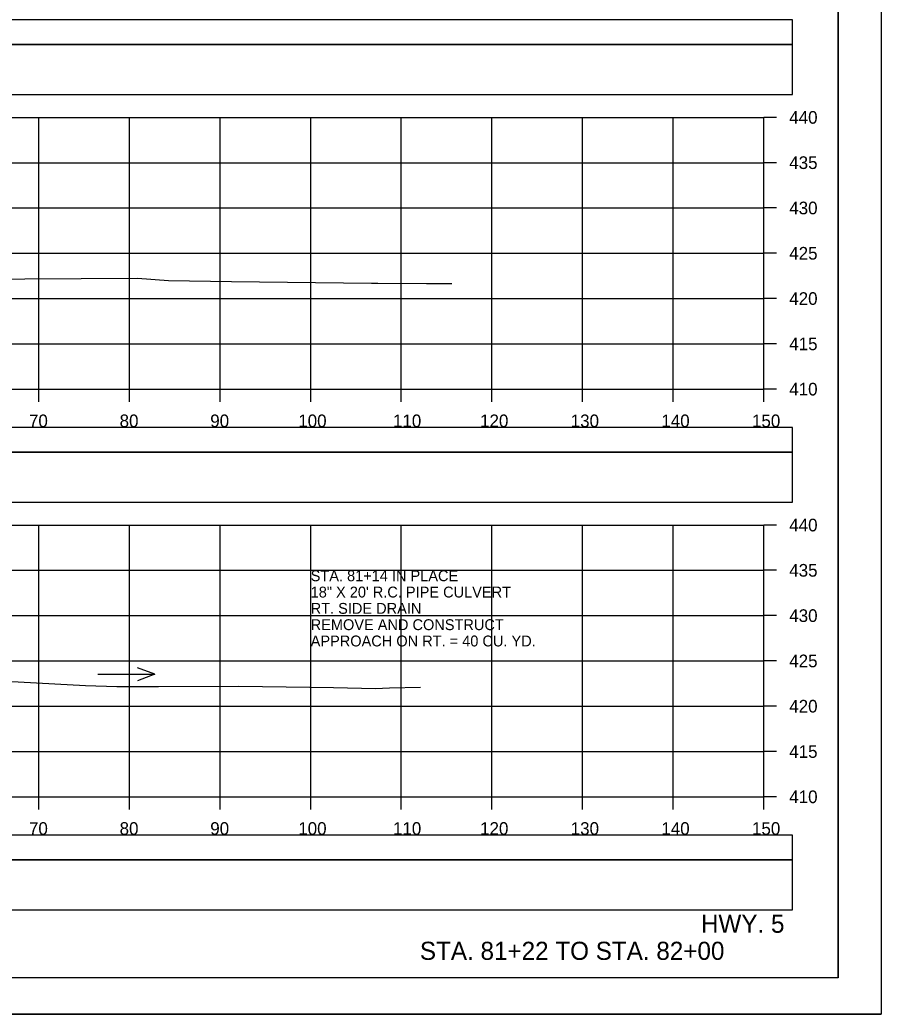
# Model space of a CAD drawing. Extents: x 1371057 to 1372761, y 380005 to 390517.
# Drawn here: x 1371628.8 to 1371723.8, y 387898.6 to 388008.3 of the extents above; entities that cross this region are included whole.
import ezdxf

# ---------------------------------------------------------------- set-up
doc = ezdxf.new("R2010")
doc.units = 0
for name, color, linetype in [('R_Axis', 7, 'Continuous'), ('R_Axis Annot', 7, 'Continuous'), ('R_Border', 7, 'Continuous'), ('R_Detour', 7, 'Continuous'), ('R_Dimension', 7, 'Continuous'), ('R_Draft', 7, 'Continuous'), ('R_Exist Surface', 7, 'Continuous'), ('R_Grid', 7, 'Continuous'), ('R_No Plot', 7, 'Continuous'), ('R_Water Annot', 7, 'Continuous')]:
    doc.layers.add(name, color=color, linetype=linetype)

msp = doc.modelspace()

# ---------------------------------------------------------------- linework, layer by layer
at = {"layer": 'R_Axis'}
for p, q in [((1371710.87, 387967.57), (1371710.87, 387997.57)), ((1371712.27, 387997.57), (1371710.87, 387997.57)), ((1371712.27, 387992.57), (1371710.87, 387992.57)), ((1371712.27, 387987.57), (1371710.87, 387987.57)), ((1371712.27, 387982.57), (1371710.87, 387982.57)), ((1371712.27, 387977.57), (1371710.87, 387977.57)), ((1371712.27, 387972.57), (1371710.87, 387972.57)), ((1371410.87, 387967.57), (1371710.87, 387967.57)), ((1371630.87, 387966.17), (1371630.87, 387967.57)), ((1371640.87, 387966.17), (1371640.87, 387967.57)), ((1371650.87, 387966.17), (1371650.87, 387967.57)), ((1371660.87, 387966.17), (1371660.87, 387967.57)), ((1371670.87, 387966.17), (1371670.87, 387967.57)), ((1371680.87, 387966.17), (1371680.87, 387967.57)), ((1371690.87, 387966.17), (1371690.87, 387967.57)), ((1371700.87, 387966.17), (1371700.87, 387967.57)), ((1371710.87, 387966.17), (1371710.87, 387967.57)), ((1371712.27, 387967.57), (1371710.87, 387967.57)), ((1371710.87, 387922.57), (1371710.87, 387952.57)), ((1371712.27, 387952.57), (1371710.87, 387952.57)), ((1371712.27, 387947.57), (1371710.87, 387947.57)), ((1371712.27, 387942.57), (1371710.87, 387942.57)), ((1371712.27, 387937.57), (1371710.87, 387937.57)), ((1371712.27, 387932.57), (1371710.87, 387932.57)), ((1371712.27, 387927.57), (1371710.87, 387927.57)), ((1371410.87, 387922.57), (1371710.87, 387922.57)), ((1371630.87, 387921.17), (1371630.87, 387922.57)), ((1371640.87, 387921.17), (1371640.87, 387922.57)), ((1371650.87, 387921.17), (1371650.87, 387922.57)), ((1371660.87, 387921.17), (1371660.87, 387922.57)), ((1371670.87, 387921.17), (1371670.87, 387922.57)), ((1371680.87, 387921.17), (1371680.87, 387922.57)), ((1371690.87, 387921.17), (1371690.87, 387922.57)), ((1371700.87, 387921.17), (1371700.87, 387922.57)), ((1371710.87, 387921.17), (1371710.87, 387922.57)), ((1371712.27, 387922.57), (1371710.87, 387922.57))]:
    msp.add_line(p, q, dxfattribs=at)
at = {"layer": 'R_Border'}
for q in [(1371719.05, 388108.03), (1371402.87, 387902.57)]:
    msp.add_line((1371719.05, 387902.57), q, dxfattribs=at)
at = {"layer": 'R_Detour'}
for points in [[(1371407.72, 388005.61), (1371714.03, 388005.61), (1371714.03, 388008.32), (1371407.72, 388008.32)], [(1371407.72, 387960.61), (1371714.03, 387960.61), (1371714.03, 387963.32), (1371407.72, 387963.32)], [(1371407.72, 387915.61), (1371714.03, 387915.61), (1371714.03, 387918.32), (1371407.72, 387918.32)]]:
    msp.add_lwpolyline(points, close=True, dxfattribs=at)
at = {"layer": 'R_Dimension'}
for points in [[(1371407.72, 388000.09), (1371714.03, 388000.09), (1371714.03, 388005.61), (1371407.72, 388005.61)], [(1371407.72, 387955.09), (1371714.03, 387955.09), (1371714.03, 387960.61), (1371407.72, 387960.61)], [(1371407.72, 387910.09), (1371714.03, 387910.09), (1371714.03, 387915.61), (1371407.72, 387915.61)]]:
    msp.add_lwpolyline(points, close=True, dxfattribs=at)
at = {"layer": 'R_Exist Surface'}
for points in [[(1371627.43, 387979.72), (1371629.33, 387979.74), (1371641.76, 387979.83), (1371645.19, 387979.58), (1371652.13, 387979.44), (1371667.57, 387979.28), (1371668.16, 387979.28), (1371668.27, 387979.27), (1371673.65, 387979.22), (1371676.43, 387979.24)], [(1371621.78, 387935.62), (1371636.01, 387934.86), (1371639.5, 387934.73), (1371644.08, 387934.73), (1371652.94, 387934.78), (1371663.38, 387934.64), (1371668.01, 387934.53), (1371669.57, 387934.61), (1371672.98, 387934.67)]]:
    msp.add_lwpolyline(points, dxfattribs=at)
at = {"layer": 'R_Grid'}
for p, q in [((1371410.87, 387997.57), (1371710.87, 387997.57)), ((1371630.87, 387967.57), (1371630.87, 387997.57)), ((1371640.87, 387967.57), (1371640.87, 387997.57)), ((1371650.87, 387967.57), (1371650.87, 387997.57)), ((1371660.87, 387967.57), (1371660.87, 387997.57)), ((1371670.87, 387967.57), (1371670.87, 387997.57)), ((1371680.87, 387967.57), (1371680.87, 387997.57)), ((1371690.87, 387967.57), (1371690.87, 387997.57)), ((1371700.87, 387967.57), (1371700.87, 387997.57)), ((1371710.87, 387967.57), (1371710.87, 387997.57)), ((1371410.87, 387992.57), (1371710.87, 387992.57)), ((1371410.87, 387987.57), (1371710.87, 387987.57)), ((1371410.87, 387982.57), (1371710.87, 387982.57)), ((1371410.87, 387977.57), (1371710.87, 387977.57)), ((1371410.87, 387972.57), (1371710.87, 387972.57)), ((1371410.87, 387967.57), (1371710.87, 387967.57)), ((1371410.87, 387952.57), (1371710.87, 387952.57)), ((1371630.87, 387922.57), (1371630.87, 387952.57)), ((1371640.87, 387922.57), (1371640.87, 387952.57)), ((1371650.87, 387922.57), (1371650.87, 387952.57)), ((1371660.87, 387922.57), (1371660.87, 387952.57)), ((1371670.87, 387922.57), (1371670.87, 387952.57)), ((1371680.87, 387922.57), (1371680.87, 387952.57)), ((1371690.87, 387922.57), (1371690.87, 387952.57)), ((1371700.87, 387922.57), (1371700.87, 387952.57)), ((1371710.87, 387922.57), (1371710.87, 387952.57)), ((1371410.87, 387947.57), (1371710.87, 387947.57)), ((1371410.87, 387942.57), (1371710.87, 387942.57)), ((1371410.87, 387937.57), (1371710.87, 387937.57)), ((1371410.87, 387932.57), (1371710.87, 387932.57)), ((1371410.87, 387927.57), (1371710.87, 387927.57)), ((1371410.87, 387922.57), (1371710.87, 387922.57))]:
    msp.add_line(p, q, dxfattribs=at)
at = {"layer": 'R_No Plot'}
msp.add_line((1371390.47, 387898.59), (1371723.8, 387898.59), dxfattribs=at)
for points in [[(1371390.46, 388111.92), (1371723.8, 388111.92), (1371723.8, 387898.58), (1371390.46, 387898.58)], [(1371636.79, 388108.03), (1371656.41, 388108.03), (1371656.41, 388098.15), (1371672.52, 388098.15), (1371695.72, 388098.15), (1371695.84, 388069.99), (1371719.05, 388069.99), (1371719.05, 387902.57), (1371402.87, 387902.57), (1371402.87, 388108.03)]]:
    msp.add_lwpolyline(points, close=True, dxfattribs=at)
at = {"layer": 'R_Water Annot'}
for p, q in [((1371637.39, 387936.09), (1371643.67, 387936.09)), ((1371643.67, 387936.09), (1371641.75, 387936.79)), ((1371643.67, 387936.09), (1371641.75, 387935.39))]:
    msp.add_line(p, q, dxfattribs=at)

# ---------------------------------------------------------------- texts
at = {"layer": 'R_Axis Annot'}
for s, p in [('440', (1371713.67, 387996.87)), ('435', (1371713.67, 387991.87)), ('430', (1371713.67, 387986.87)), ('425', (1371713.67, 387981.87)), ('420', (1371713.67, 387976.87)), ('415', (1371713.67, 387971.87)), ('410', (1371713.67, 387966.87)), ('70', (1371629.79, 387963.37)), ('80', (1371639.79, 387963.37)), ('90', (1371649.79, 387963.37)), ('100', (1371659.5, 387963.37)), ('110', (1371669.95, 387963.37)), ('120', (1371679.56, 387963.37)), ('130', (1371689.56, 387963.37)), ('140', (1371699.56, 387963.37)), ('150', (1371709.56, 387963.37)), ('440', (1371713.67, 387951.87)), ('435', (1371713.67, 387946.87)), ('430', (1371713.67, 387941.87)), ('425', (1371713.67, 387936.87)), ('420', (1371713.67, 387931.87)), ('415', (1371713.67, 387926.87)), ('410', (1371713.67, 387921.87)), ('70', (1371629.79, 387918.37)), ('80', (1371639.79, 387918.37)), ('90', (1371649.79, 387918.37)), ('100', (1371659.5, 387918.37)), ('110', (1371669.95, 387918.37)), ('120', (1371679.56, 387918.37)), ('130', (1371689.56, 387918.37)), ('140', (1371699.56, 387918.37)), ('150', (1371709.56, 387918.37))]:
    msp.add_text(s, height=1.4, dxfattribs=at).set_placement(p)
at = {"layer": 'R_Draft'}
for s, p in [('HWY. 5', (1371703.93, 387907.56)), ('STA. 81+22 TO STA. 82+00', (1371672.92, 387904.57))]:
    msp.add_text(s, height=2, dxfattribs=at).set_placement(p)
at = {"layer": 'R_Water Annot'}
for s, p in [('STA. 81+14 IN PLACE', (1371660.87, 387946.37)), ('18" X 20\' R.C. PIPE CULVERT', (1371660.87, 387944.57)), ('RT. SIDE DRAIN', (1371660.87, 387942.77)), ('REMOVE AND CONSTRUCT', (1371660.87, 387940.97)), ('APPROACH ON RT. = 40 CU. YD.', (1371660.87, 387939.17))]:
    msp.add_text(s, height=1.2, dxfattribs=at).set_placement(p)

doc.saveas('drawing.dxf')
